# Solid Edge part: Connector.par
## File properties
Title: Connector
Author: windows
Template: Iso Metric Part.par
Last saved by: windows
Revision: 4
Application: Solid Edge
Username: windows
Density: 2712,000 kg/m^3
Accuracy: 0,990
Material: Aluminum, 3004
Face Style: Aluminum
Fill Style: ANSI38(Aluminum)
Virtual Style: ANSI38(Aluminum)
Grouping: Metals\Aluminium Alloys
LibraryName: Materials
Coef. of Thermal Exp: 2.3e-05
Thermal Conductivity: 170.0
Specific Heat: 920.0
Modulus of Elasticity: 68947570000.0
Poisson's Ratio: 0.33
Yield Stress: 68947570.0
Ultimate Stress: 179263682.0
Elongation: 0.0
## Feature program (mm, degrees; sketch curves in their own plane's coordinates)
sketch for "unnamed RevolvedProtrusion 1" plane through (0, 0, 0) normal (0, -1, 0) x-axis (1, 0, 0)
  line (5.4849, 34.9907) -> (-0.0151, 39.3208)
  line (-0.0151, 39.3208) -> (-0.0151, -0.0093)
  line (-0.0151, -0.0093) -> (2.4849, -0.0093)
  line (2.4849, -0.0093) -> (2.4849, 34.9907)
  line (2.4849, 34.9907) -> (5.4849, 34.9907)
revolve "unnamed RevolvedProtrusion 1" add full turn 360 deg about sketch line (-0.0151, 39.3208) -> (-0.0151, -0.0093)
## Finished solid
Body 1: solid body, 4 faces, 3 edges, 1 vertex.
  Faces by surface: plane 2, cone 1, cylinder 1
  Edges by curve: circle 3
Bounding box of the edges (mm): 11.000 x 11.000 x 35.000, from (-5.5151, -5.5, -0.0093) to (5.4849, 5.5, 34.9907).
Cylindrical faces by radius (mm): R2.5 x1
Conical faces (half-angle, radius in mm at the cone's reference point): 51.7868 deg R5.5 x1
Planar faces by outward normal: -z 2
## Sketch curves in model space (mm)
line (2.4849, 0, -0.0093) -> (2.4849, 0, 34.9907)
line (2.4849, 0, 34.9907) -> (5.4849, 0, 34.9907)
line (5.4849, 0, 34.9907) -> (-0.0151, 0, 39.3208)
line (-0.0151, 0, 39.3208) -> (-0.0151, 0, -0.0093)
line (-0.0151, 0, -0.0093) -> (2.4849, 0, -0.0093)
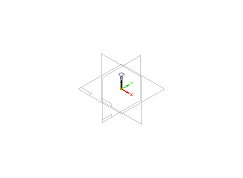
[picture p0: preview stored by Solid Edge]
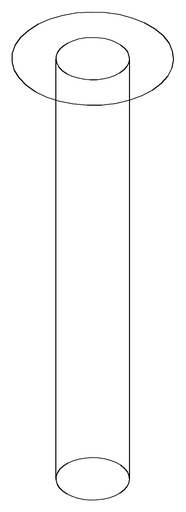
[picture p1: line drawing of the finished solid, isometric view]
